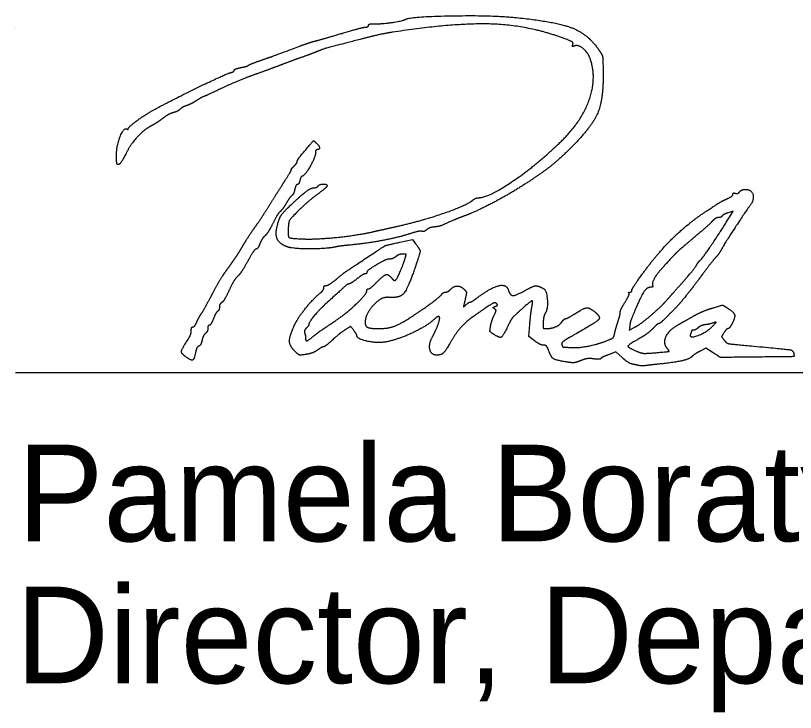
# Model space of a CAD drawing. Extents: x 0 to 34, y 0 to 22.
# Drawn here: x 24.5 to 25.63, y 7.199 to 8.208 of the extents above; entities that cross this region are included whole.
import ezdxf

# ---------------------------------------------------------------- set-up
doc = ezdxf.new("R2010")
doc.units = 0
for name, color, linetype in [('Default', 7, 'Continuous'), ('SH_Data', 7, 'Continuous'), ('SH_Text', 7, 'Continuous')]:
    doc.layers.add(name, color=color, linetype=linetype)

msp = doc.modelspace()

# ---------------------------------------------------------------- linework, layer by layer
at = {"layer": 'Default'}
for points in [[(25.5343, 7.916), (25.5396, 7.925), (25.5323, 7.9224)], [(25.0569, 7.8799), (25.0749, 7.8839), (25.0796, 7.8777)], [(25.2519, 7.7371), (25.2436, 7.7434), (25.245, 7.7605)], [(25.3899, 7.7591), (25.3889, 7.7526), (25.3975, 7.757)], [(25.3788, 7.7127), (25.3697, 7.721), (25.3591, 7.7169)], [(25.5107, 7.7197), (25.5001, 7.7265), (25.4917, 7.722)]]:
    msp.add_lwpolyline(points, dxfattribs=at)
for points in [[(25.0643, 8.2024), (25.0711, 8.2066), (25.1881, 8.2089), (25.2225, 8.2055)], [(25.2225, 8.2055), (25.2818, 8.1997), (25.3293, 8.1814), (25.3451, 8.1584)], [(25.0076, 8.1915), (25.0097, 8.1915), (25.0113, 8.1926), (25.0113, 8.194)], [(25.0113, 8.194), (25.0113, 8.1954), (25.0154, 8.1964), (25.0203, 8.1962)], [(25.0203, 8.1962), (25.0299, 8.196), (25.0609, 8.2003), (25.0643, 8.2024)], [(25.295, 8.1748), (25.2445, 8.1938), (25.1365, 8.1978), (25.0461, 8.184)], [(24.9357, 8.1717), (24.941, 8.1731), (24.9585, 8.1781), (24.9746, 8.1829)], [(24.9746, 8.1829), (24.9907, 8.1876), (25.0055, 8.1915), (25.0076, 8.1915)], [(25.0461, 8.184), (25.0369, 8.1826), (25.0169, 8.1782), (25.0017, 8.1743)], [(24.9117, 8.1639), (24.9197, 8.1668), (24.9305, 8.1704), (24.9357, 8.1717)], [(25.0017, 8.1743), (24.9507, 8.1611), (24.9465, 8.1599), (24.9357, 8.1555)], [(25.3074, 8.1662), (25.3083, 8.1687), (25.3049, 8.1711), (25.295, 8.1748)], [(24.8553, 8.1433), (24.8701, 8.1484), (24.8765, 8.1507), (24.9117, 8.1639)], [(25.3098, 8.1641), (25.3072, 8.1631), (25.3064, 8.1637), (25.3074, 8.1662)], [(25.3331, 8.1442), (25.3299, 8.154), (25.3154, 8.1663), (25.3098, 8.1641)], [(25.3451, 8.1584), (25.3501, 8.1511), (25.351, 8.1468), (25.3513, 8.1289)], [(24.9129, 8.147), (24.903, 8.1435), (24.8879, 8.1379), (24.8793, 8.1346)], [(24.9357, 8.1555), (24.9331, 8.1545), (24.9228, 8.1506), (24.9129, 8.147)], [(24.8259, 8.1327), (24.8309, 8.1336), (24.836, 8.1351), (24.8373, 8.1361)], [(24.8373, 8.1361), (24.8387, 8.1371), (24.8468, 8.1403), (24.8553, 8.1433)], [(25.2876, 8.023), (25.3186, 8.0524), (25.3424, 8.1159), (25.3331, 8.1442)], [(24.6993, 8.0711), (24.7296, 8.0874), (24.8032, 8.123), (24.8115, 8.1255)], [(24.8115, 8.1255), (24.8145, 8.1263), (24.8169, 8.1279), (24.8169, 8.129)], [(24.8169, 8.129), (24.8169, 8.1301), (24.821, 8.1317), (24.8259, 8.1327)], [(24.8793, 8.1346), (24.8708, 8.1314), (24.8546, 8.1255), (24.8433, 8.1215)], [(25.3513, 8.1289), (25.3521, 8.0881), (25.336, 8.0484), (25.3066, 8.0186)], [(24.8433, 8.1215), (24.8321, 8.1175), (24.8118, 8.109), (24.7981, 8.1025)], [(24.7981, 8.1025), (24.7845, 8.096), (24.7728, 8.0907), (24.7723, 8.0907)], [(24.7723, 8.0907), (24.7717, 8.0907), (24.7672, 8.0882), (24.7623, 8.0851)], [(24.7623, 8.0851), (24.7574, 8.082), (24.7507, 8.0786), (24.7475, 8.0776)], [(24.6633, 8.0445), (24.6633, 8.0466), (24.6887, 8.0654), (24.6993, 8.0711)], [(24.7383, 8.0724), (24.7365, 8.0706), (24.7321, 8.0684), (24.7286, 8.0676)], [(24.7475, 8.0776), (24.7442, 8.0765), (24.7401, 8.0742), (24.7383, 8.0724)], [(24.7137, 8.0595), (24.7091, 8.0559), (24.702, 8.0513), (24.6979, 8.0491)], [(24.7286, 8.0676), (24.725, 8.0667), (24.7184, 8.0631), (24.7137, 8.0595)], [(24.6979, 8.0491), (24.6874, 8.0438), (24.6675, 8.023), (24.6613, 8.0108)], [(24.6462, 8.0066), (24.6463, 8.0198), (24.6569, 8.0464), (24.661, 8.0439)], [(24.661, 8.0439), (24.6623, 8.0431), (24.6633, 8.0434), (24.6633, 8.0445)], [(24.9135, 8.0056), (24.9321, 8.0277), (24.9314, 8.0271), (24.9355, 8.0237)], [(24.9355, 8.0237), (24.9398, 8.0202), (24.9407, 8.0139), (24.9369, 8.0139)], [(25.1709, 7.9443), (25.185, 7.9443), (25.2531, 7.9902), (25.2876, 8.023)], [(24.9369, 8.0139), (24.9356, 8.0139), (24.9345, 8.0116), (24.9345, 8.0088)], [(25.3066, 8.0186), (25.288, 7.9997), (25.2556, 7.9748), (25.2251, 7.9559)], [(24.6475, 7.9929), (24.6467, 7.9937), (24.6461, 7.9999), (24.6462, 8.0066)], [(24.6613, 8.0108), (24.6547, 7.998), (24.6494, 7.9911), (24.6475, 7.9929)], [(24.9081, 7.9969), (24.9081, 7.9981), (24.9106, 8.002), (24.9135, 8.0056)], [(24.9345, 8.0088), (24.9345, 8.0033), (24.9186, 7.9755), (24.9154, 7.9755)], [(24.8996, 7.9851), (24.899, 7.9851), (24.9007, 7.9873), (24.9033, 7.9899)], [(24.9033, 7.9899), (24.906, 7.9926), (24.9081, 7.9957), (24.9081, 7.9969)], [(24.8906, 7.9695), (24.8961, 7.9781), (24.9002, 7.9851), (24.8996, 7.9851)], [(24.8685, 7.9344), (24.8751, 7.9451), (24.8851, 7.9608), (24.8906, 7.9695)], [(24.912, 7.9695), (24.9111, 7.9662), (24.9095, 7.9635), (24.9083, 7.9635)], [(24.9154, 7.9755), (24.9143, 7.9755), (24.9128, 7.9728), (24.912, 7.9695)], [(24.8997, 7.9346), (24.9154, 7.9492), (24.9282, 7.9587), (24.9321, 7.9587)], [(24.9045, 7.9563), (24.9037, 7.9524), (24.9019, 7.9485), (24.9007, 7.9477)], [(24.9083, 7.9635), (24.9071, 7.9635), (24.9054, 7.9603), (24.9045, 7.9563)], [(24.9321, 7.9587), (24.9346, 7.9587), (24.9373, 7.9598), (24.9381, 7.9611)], [(24.9513, 7.9615), (24.9513, 7.9604), (24.9446, 7.9545), (24.9363, 7.9484)], [(24.9381, 7.9611), (24.9399, 7.964), (24.9513, 7.9643), (24.9513, 7.9615)], [(25.2251, 7.9559), (25.2059, 7.9441), (25.1646, 7.9231), (25.1505, 7.918)], [(25.5491, 7.9529), (25.5506, 7.9548), (25.5543, 7.9563), (25.5573, 7.9563)], [(25.5573, 7.9563), (25.5667, 7.9563), (25.5704, 7.9403), (25.563, 7.9313)], [(24.9007, 7.9477), (24.8994, 7.947), (24.8956, 7.9418), (24.8922, 7.9363)], [(24.9363, 7.9484), (24.9281, 7.9423), (24.9156, 7.9314), (24.9086, 7.9242)], [(25.1627, 7.941), (25.1648, 7.9428), (25.1685, 7.9443), (25.1709, 7.9443)], [(25.5315, 7.943), (25.5358, 7.9449), (25.5393, 7.9477), (25.5393, 7.9493)], [(25.5393, 7.9493), (25.5393, 7.9508), (25.5409, 7.9514), (25.5428, 7.9507)], [(25.5428, 7.9507), (25.5447, 7.95), (25.5475, 7.951), (25.5491, 7.9529)], [(24.8468, 7.9015), (24.8522, 7.909), (24.8619, 7.9238), (24.8685, 7.9344)], [(24.8784, 7.8999), (24.8812, 7.913), (24.8873, 7.923), (24.8997, 7.9346)], [(24.8922, 7.9363), (24.8888, 7.9308), (24.8847, 7.9252), (24.883, 7.9239)], [(25.0509, 7.9024), (25.0879, 7.9106), (25.1541, 7.9335), (25.1627, 7.941)], [(25.5026, 7.9259), (25.5215, 7.9382), (25.5234, 7.9393), (25.5315, 7.943)], [(24.883, 7.9239), (24.8813, 7.9226), (24.8767, 7.9149), (24.8727, 7.9069)], [(24.9086, 7.9242), (24.8978, 7.9133), (24.8957, 7.9096), (24.8951, 7.9014)], [(25.4079, 7.8334), (25.4302, 7.8642), (25.4752, 7.9082), (25.5026, 7.9259)], [(25.563, 7.9313), (25.5589, 7.9263), (25.526, 7.8758), (25.5229, 7.8696)], [(25.5323, 7.9224), (25.5282, 7.921), (25.5243, 7.9189), (25.5236, 7.9177)], [(25.1349, 7.9118), (25.1179, 7.9043), (25.113, 7.9026), (25.1063, 7.9019)], [(25.1505, 7.918), (25.1459, 7.9163), (25.1389, 7.9135), (25.1349, 7.9118)], [(25.5094, 7.9101), (25.5067, 7.9071), (25.4943, 7.8961), (25.4817, 7.8855)], [(25.4915, 7.8531), (25.4943, 7.8551), (25.5225, 7.8966), (25.5343, 7.916)], [(25.5183, 7.9155), (25.5161, 7.9155), (25.5121, 7.9131), (25.5094, 7.9101)], [(25.5236, 7.9177), (25.5229, 7.9165), (25.5205, 7.9155), (25.5183, 7.9155)], [(24.8301, 7.8759), (24.8339, 7.8825), (24.8414, 7.894), (24.8468, 7.9015)], [(24.8727, 7.9069), (24.8686, 7.899), (24.8636, 7.891), (24.8614, 7.8892)], [(24.8937, 7.8731), (24.8833, 7.877), (24.8762, 7.8894), (24.8784, 7.8999)], [(24.8951, 7.9014), (24.8943, 7.8879), (24.8983, 7.8851), (24.9189, 7.8845)], [(25.0173, 7.8949), (25.0253, 7.8967), (25.0404, 7.9), (25.0509, 7.9024)], [(25.1063, 7.9019), (25.1025, 7.9015), (25.0976, 7.8996), (25.0955, 7.8978)], [(24.8614, 7.8892), (24.8592, 7.8874), (24.856, 7.8823), (24.8541, 7.8779)], [(24.9189, 7.8845), (24.9382, 7.884), (24.996, 7.8901), (25.0173, 7.8949)], [(25.0707, 7.8919), (25.0543, 7.8866), (25.0092, 7.8781), (24.9854, 7.8758)], [(25.0887, 7.8956), (25.0871, 7.8962), (25.079, 7.8946), (25.0707, 7.8919)], [(25.0955, 7.8978), (25.0934, 7.896), (25.0904, 7.895), (25.0887, 7.8956)], [(24.817, 7.8553), (24.8204, 7.86), (24.8262, 7.8693), (24.8301, 7.8759)], [(24.8541, 7.8779), (24.8523, 7.8735), (24.8497, 7.8699), (24.8484, 7.8699)], [(24.9854, 7.8758), (24.977, 7.875), (24.9679, 7.8739), (24.965, 7.8732)], [(25.0029, 7.8535), (25.0346, 7.8745), (25.036, 7.8752), (25.0569, 7.8799)], [(25.0796, 7.8777), (25.0862, 7.869), (25.0861, 7.8641), (25.0783, 7.8416)], [(25.4817, 7.8855), (25.4621, 7.869), (25.4504, 7.8576), (25.4337, 7.8387)], [(24.8484, 7.8699), (24.8471, 7.8699), (24.8417, 7.862), (24.8364, 7.8524)], [(24.965, 7.8732), (24.9513, 7.8702), (24.9018, 7.8701), (24.8937, 7.8731)], [(25.5229, 7.8696), (25.5211, 7.8662), (25.5172, 7.8607), (25.5142, 7.8575)], [(24.8035, 7.8361), (24.8076, 7.8419), (24.8137, 7.8505), (24.817, 7.8553)], [(24.9637, 7.8255), (24.9774, 7.8366), (24.9755, 7.8352), (25.0029, 7.8535)], [(25.0424, 7.8555), (25.0401, 7.8555), (25.0357, 7.8541), (25.0326, 7.8524)], [(25.0511, 7.859), (25.0485, 7.8571), (25.0446, 7.8555), (25.0424, 7.8555)], [(25.0496, 7.8243), (25.0514, 7.8243), (25.0611, 7.8455), (25.0643, 7.8561)], [(25.061, 7.8626), (25.0581, 7.8626), (25.0536, 7.861), (25.0511, 7.859)], [(25.0643, 7.8561), (25.066, 7.8619), (25.0656, 7.8627), (25.061, 7.8626)], [(25.4875, 7.848), (25.4887, 7.8501), (25.4905, 7.8525), (25.4915, 7.8531)], [(25.5142, 7.8575), (25.5113, 7.8543), (25.5024, 7.8429), (25.4945, 7.8323)], [(24.8364, 7.8524), (24.8311, 7.8427), (24.8244, 7.8327), (24.8215, 7.8302)], [(25.0326, 7.8524), (25.0182, 7.8444), (25.0089, 7.8381), (25.0089, 7.8361)], [(25.4562, 7.8102), (25.4716, 7.8273), (25.4851, 7.8436), (25.4875, 7.848)], [(24.7846, 7.8039), (24.7909, 7.8158), (24.7994, 7.8303), (24.8035, 7.8361)], [(25.0063, 7.8339), (25.0048, 7.8339), (24.9995, 7.8307), (24.9945, 7.8267)], [(25.0089, 7.8361), (25.0089, 7.8349), (25.0077, 7.8339), (25.0063, 7.8339)], [(25.0233, 7.8219), (25.0335, 7.832), (25.04, 7.8339), (25.0449, 7.8279)], [(25.0783, 7.8416), (25.0681, 7.8117), (25.0561, 7.7986), (25.0401, 7.8)], [(25.3929, 7.8101), (25.3929, 7.8115), (25.3997, 7.822), (25.4079, 7.8334)], [(25.4337, 7.8387), (25.4279, 7.8321), (25.4216, 7.8193), (25.4231, 7.8169)], [(25.4945, 7.8323), (25.4866, 7.8216), (25.4789, 7.8114), (25.4774, 7.8096)], [(24.8215, 7.8302), (24.8187, 7.8276), (24.8132, 7.8185), (24.8092, 7.8099)], [(24.9834, 7.8195), (24.9815, 7.8195), (24.973, 7.8122), (24.9477, 7.789)], [(24.9499, 7.8171), (24.9518, 7.8171), (24.958, 7.8209), (24.9637, 7.8255)], [(24.9945, 7.8267), (24.9895, 7.8228), (24.9845, 7.8195), (24.9834, 7.8195)], [(25.0113, 7.8123), (25.0127, 7.8123), (25.0181, 7.8166), (25.0233, 7.8219)], [(25.0449, 7.8279), (25.0466, 7.8259), (25.0487, 7.8243), (25.0496, 7.8243)], [(24.8092, 7.8099), (24.8053, 7.8013), (24.8006, 7.7935), (24.7987, 7.7924)], [(24.9411, 7.8059), (24.9441, 7.8083), (24.9465, 7.8118), (24.9465, 7.8137)], [(24.9465, 7.8137), (24.9465, 7.8156), (24.9481, 7.8171), (24.9499, 7.8171)], [(24.9629, 7.7657), (24.9785, 7.7761), (25.0089, 7.8049), (25.0089, 7.8092)], [(25.0089, 7.8092), (25.0089, 7.8109), (25.01, 7.8123), (25.0113, 7.8123)], [(25.1229, 7.8075), (25.1247, 7.8075), (25.128, 7.8093), (25.1301, 7.8114)], [(25.1301, 7.8114), (25.1351, 7.8164), (25.1451, 7.8164), (25.15, 7.8115)], [(25.15, 7.8115), (25.1532, 7.8083), (25.1534, 7.8059), (25.1513, 7.7967)], [(25.1681, 7.7988), (25.1884, 7.814), (25.2111, 7.8196), (25.2141, 7.8102)], [(25.2141, 7.8102), (25.2165, 7.8026), (25.2246, 7.8025), (25.2378, 7.8098)], [(25.2378, 7.8098), (25.2498, 7.8164), (25.257, 7.8171), (25.2653, 7.8125)], [(25.2653, 7.8125), (25.2696, 7.8101), (25.2713, 7.7821), (25.2674, 7.7769)], [(25.3901, 7.8075), (25.3917, 7.8075), (25.3929, 7.8087), (25.3929, 7.8101)], [(25.4208, 7.8147), (25.4145, 7.8147), (25.4049, 7.7995), (25.3929, 7.7703)], [(25.4231, 7.8169), (25.4238, 7.8157), (25.4228, 7.8147), (25.4208, 7.8147)], [(25.4406, 7.7927), (25.4438, 7.7962), (25.4508, 7.8041), (25.4562, 7.8102)], [(25.4774, 7.8096), (25.4642, 7.7932), (25.4596, 7.788), (25.4477, 7.7759)], [(24.7691, 7.7763), (24.7714, 7.7796), (24.7783, 7.792), (24.7846, 7.8039)], [(24.9031, 7.7576), (24.9075, 7.7681), (24.9308, 7.7976), (24.9411, 7.8059)], [(25.0401, 7.8), (25.0297, 7.8008), (25.0065, 7.7755), (25.0065, 7.7632)], [(25.0749, 7.7726), (25.0935, 7.785), (25.1159, 7.8017), (25.1177, 7.8045)], [(25.1177, 7.8045), (25.1187, 7.8061), (25.1211, 7.8075), (25.1229, 7.8075)], [(25.1513, 7.7967), (25.1489, 7.7865), (25.149, 7.786), (25.1528, 7.7894)], [(25.1587, 7.7931), (25.1597, 7.7931), (25.1639, 7.7957), (25.1681, 7.7988)], [(25.3832, 7.7932), (25.387, 7.7995), (25.3896, 7.8053), (25.3888, 7.8061)], [(25.3888, 7.8061), (25.388, 7.8069), (25.3886, 7.8075), (25.3901, 7.8075)], [(24.7953, 7.7859), (24.7953, 7.7834), (24.7942, 7.7807), (24.7928, 7.7799)], [(24.7987, 7.7924), (24.7969, 7.7913), (24.7953, 7.7884), (24.7953, 7.7859)], [(24.9477, 7.789), (24.9386, 7.7806), (24.9249, 7.7636), (24.9249, 7.7606)], [(25.1528, 7.7894), (25.1551, 7.7915), (25.1577, 7.7931), (25.1587, 7.7931)], [(25.1968, 7.791), (25.195, 7.7928), (25.1891, 7.7901), (25.1766, 7.7816)], [(25.1939, 7.7834), (25.1917, 7.7848), (25.192, 7.7857), (25.1951, 7.7869)], [(25.1951, 7.7869), (25.1981, 7.788), (25.1986, 7.7892), (25.1968, 7.791)], [(25.2379, 7.787), (25.222, 7.7729), (25.2182, 7.7685), (25.2127, 7.7572)], [(25.248, 7.7853), (25.2498, 7.7948), (25.2472, 7.7952), (25.2379, 7.787)], [(25.245, 7.7605), (25.2458, 7.7698), (25.2471, 7.781), (25.248, 7.7853)], [(25.3762, 7.7785), (25.3761, 7.7803), (25.3793, 7.7869), (25.3832, 7.7932)], [(25.4205, 7.7739), (25.4285, 7.7807), (25.4375, 7.7891), (25.4406, 7.7927)], [(25.5098, 7.7845), (25.5239, 7.7888), (25.5251, 7.7888), (25.5309, 7.7849)], [(24.7623, 7.7637), (24.7638, 7.7673), (24.7669, 7.773), (24.7691, 7.7763)], [(24.7928, 7.7799), (24.7915, 7.779), (24.7886, 7.7741), (24.7866, 7.7689)], [(25.1766, 7.7816), (25.1568, 7.7681), (25.1396, 7.7511), (25.1313, 7.7367)], [(25.1932, 7.7735), (25.1961, 7.7798), (25.1963, 7.782), (25.1939, 7.7834)], [(25.2674, 7.7769), (25.2662, 7.7753), (25.2649, 7.7696), (25.2645, 7.7643)], [(25.297, 7.7691), (25.2982, 7.7691), (25.3043, 7.7724), (25.3105, 7.7763)], [(25.3388, 7.7793), (25.3484, 7.7717), (25.3416, 7.7638), (25.31, 7.746)], [(25.3105, 7.7763), (25.3235, 7.7845), (25.3311, 7.7853), (25.3388, 7.7793)], [(25.3726, 7.7643), (25.3746, 7.7703), (25.3762, 7.7766), (25.3762, 7.7785)], [(25.4477, 7.7759), (25.4402, 7.7682), (25.4332, 7.7619), (25.4321, 7.7619)], [(25.4805, 7.7719), (25.4885, 7.7764), (25.5016, 7.7821), (25.5098, 7.7845)], [(25.5309, 7.7849), (25.5406, 7.7786), (25.543, 7.7712), (25.5383, 7.7623)], [(24.757, 7.7571), (24.7583, 7.7571), (24.7607, 7.7601), (24.7623, 7.7637)], [(24.7866, 7.7689), (24.7845, 7.7637), (24.7819, 7.7595), (24.7807, 7.7595)], [(24.9314, 7.7434), (24.9389, 7.7495), (24.9441, 7.7532), (24.9629, 7.7657)], [(25.0065, 7.7632), (25.0065, 7.758), (25.0144, 7.7547), (25.0265, 7.7547)], [(25.0265, 7.7547), (25.0395, 7.7547), (25.0586, 7.7618), (25.0749, 7.7726)], [(25.1069, 7.7685), (25.0973, 7.7593), (25.0586, 7.7405), (25.0401, 7.7361)], [(25.104, 7.7427), (25.1081, 7.7504), (25.1145, 7.7667), (25.1145, 7.7694)], [(25.1145, 7.7694), (25.1145, 7.7725), (25.1106, 7.772), (25.1069, 7.7685)], [(25.1882, 7.7579), (25.1889, 7.7621), (25.1912, 7.7691), (25.1932, 7.7735)], [(25.2645, 7.7643), (25.264, 7.7567), (25.2647, 7.7547), (25.2678, 7.7547)], [(25.2678, 7.7547), (25.2761, 7.7547), (25.2881, 7.7596), (25.2914, 7.7642)], [(25.2914, 7.7642), (25.2933, 7.7669), (25.2958, 7.7691), (25.297, 7.7691)], [(25.3679, 7.7473), (25.3686, 7.7507), (25.3707, 7.7584), (25.3726, 7.7643)], [(25.3929, 7.7703), (25.3918, 7.7677), (25.3904, 7.7626), (25.3899, 7.7591)], [(25.3975, 7.757), (25.4023, 7.7595), (25.4126, 7.767), (25.4205, 7.7739)], [(25.461, 7.7609), (25.4638, 7.7624), (25.4726, 7.7673), (25.4805, 7.7719)], [(25.5117, 7.7632), (25.5091, 7.7622), (25.5038, 7.7609), (25.4999, 7.7604)], [(25.5093, 7.7576), (25.5148, 7.7632), (25.5154, 7.7645), (25.5117, 7.7632)], [(24.7487, 7.7372), (24.7519, 7.7419), (24.7545, 7.7483), (24.7545, 7.7515)], [(24.7545, 7.7515), (24.7545, 7.7546), (24.7556, 7.7571), (24.757, 7.7571)], [(24.7785, 7.755), (24.7785, 7.7525), (24.777, 7.7492), (24.7751, 7.7476)], [(24.7807, 7.7595), (24.7795, 7.7595), (24.7785, 7.7575), (24.7785, 7.755)], [(24.9047, 7.7219), (24.8971, 7.7295), (24.8965, 7.7424), (24.9031, 7.7576)], [(24.9212, 7.7554), (24.9191, 7.7534), (24.9181, 7.7501), (24.9188, 7.7482)], [(24.9249, 7.7606), (24.9249, 7.7598), (24.9233, 7.7575), (24.9212, 7.7554)], [(24.9787, 7.7536), (24.9704, 7.7482), (24.9679, 7.7461), (24.9567, 7.7361)], [(24.9899, 7.7522), (24.9855, 7.758), (24.9854, 7.758), (24.9787, 7.7536)], [(24.9945, 7.7448), (24.9945, 7.7456), (24.9924, 7.7489), (24.9899, 7.7522)], [(25.1928, 7.7464), (25.1878, 7.7497), (25.187, 7.7516), (25.1882, 7.7579)], [(25.2127, 7.7572), (25.2061, 7.7435), (25.2012, 7.7409), (25.1928, 7.7464)], [(25.4236, 7.755), (25.4199, 7.7511), (25.4119, 7.745), (25.4056, 7.7414)], [(25.4321, 7.7619), (25.431, 7.7619), (25.4272, 7.7588), (25.4236, 7.755)], [(25.4439, 7.7265), (25.4379, 7.7339), (25.4477, 7.7536), (25.461, 7.7609)], [(25.4779, 7.7466), (25.4754, 7.74), (25.5009, 7.749), (25.5093, 7.7576)], [(25.4793, 7.7513), (25.4793, 7.7508), (25.4787, 7.7486), (25.4779, 7.7466)], [(25.4822, 7.7523), (25.4806, 7.7523), (25.4793, 7.7519), (25.4793, 7.7513)], [(25.4889, 7.7559), (25.4868, 7.7539), (25.4837, 7.7523), (25.4822, 7.7523)], [(25.4999, 7.7604), (25.4961, 7.7599), (25.4911, 7.7579), (25.4889, 7.7559)], [(25.5324, 7.7547), (25.5312, 7.7547), (25.5286, 7.7521), (25.5265, 7.7489)], [(25.5383, 7.7623), (25.5362, 7.7581), (25.5335, 7.7547), (25.5324, 7.7547)], [(24.7751, 7.7476), (24.7732, 7.7461), (24.7709, 7.7415), (24.7701, 7.7376)], [(24.9188, 7.7482), (24.9195, 7.7463), (24.9201, 7.7432), (24.9201, 7.7413)], [(24.9201, 7.7413), (24.9201, 7.7365), (24.9236, 7.7371), (24.9314, 7.7434)], [(25.0401, 7.7361), (25.0273, 7.733), (24.9947, 7.7392), (24.9945, 7.7448)], [(25.1107, 7.7163), (25.1023, 7.7163), (25.0983, 7.7321), (25.104, 7.7427)], [(25.31, 7.746), (25.2968, 7.7386), (25.2906, 7.7338), (25.2914, 7.7316)], [(25.3552, 7.7366), (25.364, 7.74), (25.3669, 7.7424), (25.3679, 7.7473)], [(25.4056, 7.7414), (25.3876, 7.731), (25.3866, 7.7277), (25.3995, 7.7221)], [(25.5265, 7.7489), (25.523, 7.7436), (25.523, 7.7427), (25.5268, 7.738)], [(24.7471, 7.7135), (24.74, 7.7184), (24.7405, 7.7251), (24.7487, 7.7372)], [(24.7654, 7.7292), (24.7636, 7.7285), (24.7615, 7.7244), (24.7607, 7.72)], [(24.7701, 7.7376), (24.7692, 7.7336), (24.7671, 7.7299), (24.7654, 7.7292)], [(24.9567, 7.7361), (24.9519, 7.7318), (24.947, 7.7283), (24.9459, 7.7283)], [(25.1313, 7.7367), (25.1232, 7.7226), (25.1168, 7.7163), (25.1107, 7.7163)], [(25.2649, 7.7307), (25.2623, 7.7307), (25.2565, 7.7336), (25.2519, 7.7371)], [(25.2724, 7.7229), (25.2705, 7.7281), (25.268, 7.7307), (25.2649, 7.7307)], [(25.2914, 7.7316), (25.2927, 7.7282), (25.2934, 7.728), (25.3053, 7.7273)], [(25.3053, 7.7273), (25.3159, 7.7267), (25.342, 7.7316), (25.3552, 7.7366)], [(25.5268, 7.738), (25.5305, 7.7334), (25.5355, 7.7324), (25.5694, 7.7293)], [(25.5694, 7.7293), (25.6184, 7.7248), (25.6267, 7.7232), (25.6276, 7.7184)], [(24.7607, 7.72), (24.7589, 7.7102), (24.7547, 7.7082), (24.7471, 7.7135)], [(24.9209, 7.7173), (24.9122, 7.716), (24.9101, 7.7166), (24.9047, 7.7219)], [(24.9374, 7.7236), (24.9339, 7.721), (24.9264, 7.7182), (24.9209, 7.7173)], [(24.9459, 7.7283), (24.9448, 7.7283), (24.941, 7.7262), (24.9374, 7.7236)], [(25.2978, 7.7064), (25.2827, 7.7088), (25.2759, 7.7133), (25.2724, 7.7229)], [(25.3995, 7.7221), (25.4064, 7.7192), (25.4128, 7.7186), (25.4263, 7.7197)], [(25.4263, 7.7197), (25.4459, 7.7213), (25.4476, 7.7219), (25.4439, 7.7265)], [(25.4917, 7.722), (25.4871, 7.7195), (25.4818, 7.716), (25.48, 7.7142)], [(25.5573, 7.7133), (25.5216, 7.7129), (25.5213, 7.713), (25.5107, 7.7197)], [(25.6276, 7.7184), (25.6284, 7.7142), (25.6265, 7.714), (25.5573, 7.7133)], [(25.3189, 7.7083), (25.3119, 7.7055), (25.3063, 7.705), (25.2978, 7.7064)], [(25.3377, 7.7109), (25.332, 7.7116), (25.3247, 7.7107), (25.3189, 7.7083)], [(25.3478, 7.7112), (25.3474, 7.7103), (25.3429, 7.7102), (25.3377, 7.7109)], [(25.3591, 7.7169), (25.3533, 7.7147), (25.3482, 7.7121), (25.3478, 7.7112)], [(25.3935, 7.7033), (25.3905, 7.7039), (25.3839, 7.7082), (25.3788, 7.7127)], [(25.48, 7.7142), (25.4762, 7.7105), (25.4548, 7.7056), (25.4313, 7.7032)], [(25.4037, 7.7011), (25.4011, 7.7017), (25.3965, 7.7026), (25.3935, 7.7033)], [(25.4121, 7.7009), (25.4102, 7.7005), (25.4064, 7.7006), (25.4037, 7.7011)], [(25.4313, 7.7032), (25.4228, 7.7023), (25.4141, 7.7012), (25.4121, 7.7009)]]:
    msp.add_open_spline(points, degree=2, dxfattribs=at)
at = {"layer": 'SH_Data'}
for p, q in [((24.5, 8.191), (24.5, 8.191)), ((24.5, 7.691), (28, 7.691))]:
    msp.add_line(p, q, dxfattribs=at)

# ---------------------------------------------------------------- texts
at = {"layer": 'SH_Text'}
for s, p in [('Pamela Boratyn', (24.5024, 7.4466)), ('Director, Department of Transportation', (24.5, 7.241))]:
    msp.add_text(s, height=0.14, dxfattribs=at).set_placement(p)

doc.saveas('drawing.dxf')
